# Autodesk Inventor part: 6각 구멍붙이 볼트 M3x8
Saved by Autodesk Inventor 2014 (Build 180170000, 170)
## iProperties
Created: 2026-06
Part Number: 6각 구멍붙이 볼트 M3x8
Material: 강철, 연강
Document SubType Name: Modeling
Designer: dg
Density: 7.86 g/cm^3
Appearance: 강철
Mass: 0.929844 g
Surface Area: 1.83001 cm^2
Volume: 0.118301 cm^3
Author: jhkim
Description: 6각머리 태핑 나사
Creation Date: 2026-05-29
Sending System: Autodesk Inventor 2027
Preprocessor: ST-DEVELOPER v20.1
Author: dg
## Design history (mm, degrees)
node "6각 구멍붙이 볼트 M3x81"
body "Solid1"
node "기준1"
